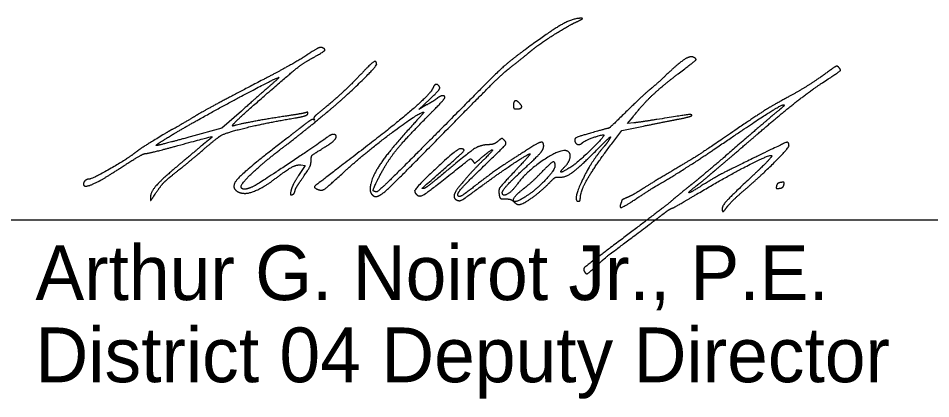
# Model space of a CAD drawing. Extents: x -37878.7 to -37844.7, y -19791.4 to -19769.4.
# Drawn here: x -37851.213 to -37848.88, y -19789.338 to -19788.365 of the extents above; entities that cross this region are included whole.
import ezdxf

# ---------------------------------------------------------------- set-up
doc = ezdxf.new("R2010")
doc.units = 0
doc.layers.add('SH_Data', color=7, linetype='Continuous')
doc.layers.add('SH_Text', color=7, linetype='Continuous')

msp = doc.modelspace()

# ---------------------------------------------------------------- linework, layer by layer
at = {"layer": 'SH_Data'}
msp.add_line((-37851.5558, -19788.88), (-37847.548, -19788.88), dxfattribs=at)
at = {"layer": 'SH_Text'}
for points in [[(-37850.1687, -19788.5865), (-37850.189, -19788.598), (-37850.1608, -19788.5717)], [(-37850.6424, -19788.6021), (-37850.692, -19788.6462), (-37850.7735, -19788.6683)], [(-37849.6391, -19788.6324), (-37849.6551, -19788.6343), (-37849.6411, -19788.6166)], [(-37849.6931, -19788.6823), (-37849.6701, -19788.6519), (-37849.614, -19788.6405)], [(-37850.4902, -19788.7399), (-37850.4796, -19788.7412), (-37850.4963, -19788.7671)]]:
    msp.add_lwpolyline(points, dxfattribs=at)
for points in [[(-37849.7722, -19788.3649), (-37849.7935, -19788.3641), (-37849.8501, -19788.3958), (-37849.9216, -19788.4485)], [(-37849.8997, -19788.4464), (-37849.8824, -19788.4317), (-37849.8072, -19788.384), (-37849.7868, -19788.3747)], [(-37849.7868, -19788.3747), (-37849.7751, -19788.3694), (-37849.7686, -19788.365), (-37849.7722, -19788.3649)], [(-37850.4368, -19788.4396), (-37850.4404, -19788.4382), (-37850.4559, -19788.446), (-37850.4743, -19788.4584)], [(-37850.458, -19788.465), (-37850.4327, -19788.4511), (-37850.4264, -19788.4436), (-37850.4368, -19788.4396)], [(-37849.9216, -19788.4485), (-37849.9599, -19788.4768), (-37850.0004, -19788.5151), (-37850.13, -19788.6461)], [(-37849.9619, -19788.4963), (-37849.9396, -19788.479), (-37849.9126, -19788.4573), (-37849.8997, -19788.4464)], [(-37850.4743, -19788.4584), (-37850.4916, -19788.4701), (-37850.5425, -19788.4988), (-37850.5876, -19788.5222)], [(-37850.5804, -19788.5604), (-37850.5157, -19788.5041), (-37850.4838, -19788.4792), (-37850.458, -19788.465)], [(-37849.4882, -19788.464), (-37849.4962, -19788.4609), (-37849.5269, -19788.4818), (-37849.558, -19788.5115)], [(-37849.5257, -19788.5069), (-37849.4838, -19788.4752), (-37849.4776, -19788.4681), (-37849.4882, -19788.464)], [(-37850.4215, -19788.6034), (-37850.3837, -19788.5722), (-37850.2969, -19788.4883), (-37850.2969, -19788.4828)], [(-37850.2969, -19788.4828), (-37850.2969, -19788.4721), (-37850.3116, -19788.4809), (-37850.3347, -19788.5057)], [(-37850.114, -19788.6466), (-37850.0415, -19788.5726), (-37849.973, -19788.505), (-37849.9619, -19788.4963)], [(-37849.1355, -19788.4966), (-37849.165, -19788.5184), (-37849.2162, -19788.5511), (-37849.2441, -19788.5662)], [(-37849.1568, -19788.5298), (-37849.1139, -19788.5016), (-37849.1088, -19788.4966), (-37849.1157, -19788.4898)], [(-37849.1157, -19788.4898), (-37849.1189, -19788.4866), (-37849.1244, -19788.4885), (-37849.1355, -19788.4966)], [(-37850.751, -19788.6234), (-37850.674, -19788.5806), (-37850.5486, -19788.5147), (-37850.547, -19788.5163)], [(-37850.547, -19788.5163), (-37850.5464, -19788.5168), (-37850.5565, -19788.5265), (-37850.5694, -19788.5377)], [(-37850.3347, -19788.5057), (-37850.3599, -19788.5327), (-37850.4158, -19788.584), (-37850.4444, -19788.6065)], [(-37849.6411, -19788.6166), (-37849.6163, -19788.5851), (-37849.5671, -19788.5383), (-37849.5257, -19788.5069)], [(-37849.558, -19788.5115), (-37849.5714, -19788.5243), (-37849.5888, -19788.5399), (-37849.5966, -19788.5461)], [(-37850.5876, -19788.5222), (-37850.6636, -19788.5618), (-37850.7426, -19788.6041), (-37850.757, -19788.613)], [(-37850.5694, -19788.5377), (-37850.5823, -19788.5488), (-37850.6152, -19788.5779), (-37850.6424, -19788.6021)], [(-37850.1524, -19788.5427), (-37850.1577, -19788.557), (-37850.2516, -19788.6383), (-37850.3463, -19788.7107)], [(-37850.1608, -19788.5717), (-37850.1432, -19788.5552), (-37850.1338, -19788.5435), (-37850.1356, -19788.5405)], [(-37850.1356, -19788.5405), (-37850.14, -19788.5333), (-37850.1494, -19788.5346), (-37850.1524, -19788.5427)], [(-37849.3198, -19788.6584), (-37849.2655, -19788.6114), (-37849.1892, -19788.5512), (-37849.1568, -19788.5298)], [(-37850.6624, -19788.64), (-37850.6709, -19788.6428), (-37850.6353, -19788.6082), (-37850.5804, -19788.5604)], [(-37850.1219, -19788.5676), (-37850.1219, -19788.5622), (-37850.1347, -19788.5635), (-37850.1419, -19788.5695)], [(-37849.5966, -19788.5461), (-37849.6045, -19788.5523), (-37849.631, -19788.577), (-37849.6557, -19788.6011)], [(-37849.2441, -19788.5662), (-37849.2839, -19788.5876), (-37849.314, -19788.6063), (-37849.3747, -19788.6476)], [(-37850.1699, -19788.6195), (-37850.1435, -19788.5929), (-37850.1219, -19788.5695), (-37850.1219, -19788.5676)], [(-37850.1419, -19788.5695), (-37850.1454, -19788.5725), (-37850.1575, -19788.5801), (-37850.1687, -19788.5865)], [(-37849.9317, -19788.5816), (-37849.9391, -19788.5741), (-37849.9468, -19788.5778), (-37849.9468, -19788.5888)], [(-37849.9468, -19788.5888), (-37849.9468, -19788.5939), (-37849.944, -19788.5967), (-37849.9389, -19788.5967)], [(-37849.9389, -19788.5967), (-37849.9279, -19788.5967), (-37849.9242, -19788.589), (-37849.9317, -19788.5816)], [(-37849.4358, -19788.7013), (-37849.3296, -19788.6289), (-37849.2546, -19788.5815), (-37849.2546, -19788.5868)], [(-37849.2546, -19788.5868), (-37849.2546, -19788.5882), (-37849.2597, -19788.5933), (-37849.2658, -19788.5981)], [(-37850.757, -19788.613), (-37850.774, -19788.6234), (-37850.819, -19788.6496), (-37850.82, -19788.6496)], [(-37850.5412, -19788.699), (-37850.5022, -19788.6692), (-37850.4746, -19788.6471), (-37850.4215, -19788.6034)], [(-37850.4786, -19788.6063), (-37850.4828, -19788.6076), (-37850.5047, -19788.6114), (-37850.5271, -19788.6148)], [(-37850.5059, -19788.6198), (-37850.4879, -19788.6168), (-37850.4738, -19788.6123), (-37850.4728, -19788.6093)], [(-37850.4728, -19788.6093), (-37850.4716, -19788.6057), (-37850.4735, -19788.6047), (-37850.4786, -19788.6063)], [(-37850.4444, -19788.6065), (-37850.4527, -19788.613), (-37850.4584, -19788.6201), (-37850.457, -19788.6224)], [(-37850.3788, -19788.7567), (-37850.3277, -19788.7099), (-37850.1876, -19788.6048), (-37850.1763, -19788.6048)], [(-37850.1763, -19788.6048), (-37850.1751, -19788.6048), (-37850.1872, -19788.619), (-37850.2032, -19788.6364)], [(-37849.6557, -19788.6011), (-37849.6996, -19788.644), (-37849.7011, -19788.645), (-37849.7321, -19788.6536)], [(-37849.4908, -19788.6131), (-37849.4908, -19788.6102), (-37849.5075, -19788.6122), (-37849.5804, -19788.6237)], [(-37849.5244, -19788.6225), (-37849.5059, -19788.6189), (-37849.4908, -19788.6147), (-37849.4908, -19788.6131)], [(-37849.2658, -19788.5981), (-37849.2719, -19788.6029), (-37849.3109, -19788.6362), (-37849.3524, -19788.672)], [(-37850.8598, -19788.6903), (-37850.8643, -19788.6903), (-37850.7979, -19788.6495), (-37850.751, -19788.6234)], [(-37850.698, -19788.6667), (-37850.6861, -19788.6582), (-37850.581, -19788.6325), (-37850.5059, -19788.6198)], [(-37850.5271, -19788.6148), (-37850.5705, -19788.6212), (-37850.6507, -19788.6362), (-37850.6624, -19788.64)], [(-37850.4583, -19788.6241), (-37850.4604, -19788.6228), (-37850.4712, -19788.6289), (-37850.4824, -19788.6377)], [(-37850.457, -19788.6224), (-37850.4556, -19788.6246), (-37850.4562, -19788.6254), (-37850.4583, -19788.6241)], [(-37850.2032, -19788.6364), (-37850.2623, -19788.7003), (-37850.3132, -19788.7767), (-37850.3132, -19788.8014)], [(-37850.2914, -19788.7729), (-37850.2717, -19788.7339), (-37850.226, -19788.6761), (-37850.1699, -19788.6195)], [(-37849.5804, -19788.6237), (-37849.6039, -19788.6274), (-37849.6303, -19788.6313), (-37849.6391, -19788.6324)], [(-37849.614, -19788.6405), (-37849.5832, -19788.6342), (-37849.5428, -19788.6261), (-37849.5244, -19788.6225)], [(-37850.82, -19788.6496), (-37850.8206, -19788.6496), (-37850.831, -19788.6557), (-37850.843, -19788.663)], [(-37850.4824, -19788.6377), (-37850.4935, -19788.6466), (-37850.5126, -19788.6615), (-37850.5249, -19788.6709)], [(-37850.2984, -19788.8206), (-37850.288, -19788.8206), (-37850.2425, -19788.7777), (-37850.114, -19788.6466)], [(-37850.13, -19788.6461), (-37850.2185, -19788.7354), (-37850.293, -19788.8085), (-37850.2957, -19788.8085)], [(-37849.7321, -19788.6536), (-37849.7779, -19788.6662), (-37849.7923, -19788.6729), (-37849.7895, -19788.6802)], [(-37849.3747, -19788.6476), (-37849.4633, -19788.7078), (-37849.4825, -19788.7202), (-37849.5417, -19788.7554)], [(-37849.3727, -19788.7037), (-37849.3492, -19788.6836), (-37849.3254, -19788.6633), (-37849.3198, -19788.6584)], [(-37850.843, -19788.663), (-37850.8944, -19788.6946), (-37850.9019, -19788.6995), (-37850.9181, -19788.7118)], [(-37850.7735, -19788.6683), (-37850.8183, -19788.6804), (-37850.8571, -19788.6903), (-37850.8598, -19788.6903)], [(-37850.8046, -19788.6903), (-37850.7239, -19788.6685), (-37850.7135, -19788.6666), (-37850.7265, -19788.6764)], [(-37850.7463, -19788.7063), (-37850.7264, -19788.6894), (-37850.7047, -19788.6716), (-37850.698, -19788.6667)], [(-37850.7265, -19788.6764), (-37850.7309, -19788.6798), (-37850.7383, -19788.6857), (-37850.7427, -19788.6895)], [(-37850.5249, -19788.6709), (-37850.6297, -19788.7512), (-37850.672, -19788.7973), (-37850.6512, -19788.8084)], [(-37850.4239, -19788.6696), (-37850.4425, -19788.684), (-37850.5965, -19788.7869), (-37850.6092, -19788.7935)], [(-37850.4384, -19788.7), (-37850.4244, -19788.6915), (-37850.4107, -19788.6823), (-37850.4079, -19788.6796)], [(-37850.4079, -19788.6796), (-37850.3953, -19788.6673), (-37850.4094, -19788.6584), (-37850.4239, -19788.6696)], [(-37850.0152, -19788.7357), (-37849.9731, -19788.6952), (-37849.9638, -19788.6842), (-37849.9675, -19788.6797)], [(-37849.9883, -19788.6809), (-37849.9925, -19788.6847), (-37850.0027, -19788.6879), (-37850.0111, -19788.6881)], [(-37849.9675, -19788.6797), (-37849.9737, -19788.6722), (-37849.9791, -19788.6726), (-37849.9883, -19788.6809)], [(-37849.8695, -19788.6912), (-37849.8694, -19788.6819), (-37849.8801, -19788.6816), (-37849.8943, -19788.6904)], [(-37849.7159, -19788.6634), (-37849.713, -19788.6662), (-37849.7837, -19788.7349), (-37849.8001, -19788.7453)], [(-37849.7895, -19788.6802), (-37849.7868, -19788.6871), (-37849.7754, -19788.6883), (-37849.7694, -19788.6823)], [(-37849.7758, -19788.8246), (-37849.7758, -19788.807), (-37849.7375, -19788.7411), (-37849.6931, -19788.6823)], [(-37849.7694, -19788.6823), (-37849.7646, -19788.6776), (-37849.7181, -19788.6611), (-37849.7159, -19788.6634)], [(-37849.7292, -19788.6969), (-37849.7092, -19788.6765), (-37849.6962, -19788.6653), (-37849.7003, -19788.672)], [(-37849.7003, -19788.672), (-37849.7043, -19788.6787), (-37849.7109, -19788.6879), (-37849.7148, -19788.6924)], [(-37849.3524, -19788.672), (-37849.4211, -19788.7313), (-37849.4748, -19788.7768), (-37849.4908, -19788.7893)], [(-37849.2424, -19788.6908), (-37849.2424, -19788.68), (-37849.2563, -19788.6848), (-37849.3309, -19788.7212)], [(-37850.8874, -19788.7107), (-37850.8832, -19788.7107), (-37850.8459, -19788.7015), (-37850.8046, -19788.6903)], [(-37850.8013, -19788.7519), (-37850.7909, -19788.7438), (-37850.7662, -19788.7233), (-37850.7463, -19788.7063)], [(-37850.7427, -19788.6895), (-37850.7472, -19788.6934), (-37850.7731, -19788.7153), (-37850.8004, -19788.7382)], [(-37850.643, -19788.7951), (-37850.643, -19788.7874), (-37850.5848, -19788.7324), (-37850.5412, -19788.699)], [(-37850.4639, -19788.7254), (-37850.4639, -19788.7174), (-37850.4586, -19788.7122), (-37850.4384, -19788.7)], [(-37850.0835, -19788.6985), (-37850.0907, -19788.6985), (-37850.1991, -19788.7998), (-37850.1992, -19788.8066)], [(-37850.0111, -19788.6881), (-37850.0317, -19788.6886), (-37850.0632, -19788.7096), (-37850.1439, -19788.7768)], [(-37850.1165, -19788.7434), (-37850.0785, -19788.7101), (-37850.0699, -19788.6985), (-37850.0835, -19788.6985)], [(-37850.032, -19788.724), (-37850.0057, -19788.7012), (-37849.9968, -19788.7011), (-37850.0201, -19788.7239)], [(-37849.8943, -19788.6904), (-37849.9502, -19788.7253), (-37850.0034, -19788.7612), (-37850.03, -19788.7819)], [(-37849.8101, -19788.7041), (-37849.8261, -19788.698), (-37849.9149, -19788.7576), (-37849.9375, -19788.7897)], [(-37849.908, -19788.7389), (-37849.8846, -19788.7174), (-37849.8696, -19788.6987), (-37849.8695, -19788.6912)], [(-37849.8292, -19788.771), (-37849.8144, -19788.7726), (-37849.7745, -19788.743), (-37849.7292, -19788.6969)], [(-37849.8152, -19788.7441), (-37849.8031, -19788.7314), (-37849.8001, -19788.708), (-37849.8101, -19788.7041)], [(-37849.7148, -19788.6924), (-37849.7481, -19788.7303), (-37849.796, -19788.8328), (-37849.7804, -19788.8328)], [(-37849.5824, -19788.7939), (-37849.5597, -19788.7814), (-37849.4717, -19788.7258), (-37849.4358, -19788.7013)], [(-37849.4375, -19788.759), (-37849.4254, -19788.7486), (-37849.3962, -19788.7237), (-37849.3727, -19788.7037)], [(-37849.3585, -19788.806), (-37849.3178, -19788.7711), (-37849.2424, -19788.6962), (-37849.2424, -19788.6908)], [(-37850.9181, -19788.7118), (-37850.9373, -19788.7265), (-37851.0233, -19788.7758), (-37851.0297, -19788.7758)], [(-37850.942, -19788.7413), (-37850.9161, -19788.7245), (-37850.8916, -19788.7107), (-37850.8874, -19788.7107)], [(-37850.4902, -19788.7794), (-37850.4717, -19788.7535), (-37850.4639, -19788.7373), (-37850.4639, -19788.7254)], [(-37850.3463, -19788.7107), (-37850.4516, -19788.7912), (-37850.4587, -19788.7978), (-37850.4458, -19788.8028)], [(-37850.1074, -19788.7633), (-37850.0614, -19788.7266), (-37850.0555, -19788.723), (-37850.051, -19788.7292)], [(-37850.0201, -19788.7239), (-37850.0415, -19788.7448), (-37850.0646, -19788.7699), (-37850.0841, -19788.7933)], [(-37850.051, -19788.7292), (-37850.0463, -19788.7355), (-37850.0447, -19788.7351), (-37850.032, -19788.724)], [(-37850.0268, -19788.7925), (-37849.983, -19788.7602), (-37849.9061, -19788.7093), (-37849.9041, -19788.7113)], [(-37849.9041, -19788.7113), (-37849.9034, -19788.7121), (-37849.92, -19788.731), (-37849.9411, -19788.7534)], [(-37849.4786, -19788.8148), (-37849.3969, -19788.7661), (-37849.2813, -19788.7078), (-37849.2868, -19788.718)], [(-37849.3309, -19788.7212), (-37849.4051, -19788.7575), (-37849.4343, -19788.7732), (-37849.4759, -19788.7992)], [(-37849.2868, -19788.718), (-37849.2891, -19788.7224), (-37849.3149, -19788.7484), (-37849.3441, -19788.7759)], [(-37851.0079, -19788.782), (-37850.9974, -19788.7764), (-37850.9678, -19788.7581), (-37850.942, -19788.7413)], [(-37850.8004, -19788.7382), (-37850.8458, -19788.7764), (-37850.8751, -19788.8098), (-37850.8751, -19788.8233)], [(-37850.8608, -19788.8115), (-37850.8486, -19788.7928), (-37850.831, -19788.7751), (-37850.8013, -19788.7519)], [(-37850.5575, -19788.7762), (-37850.527, -19788.7527), (-37850.5009, -19788.7386), (-37850.4902, -19788.7399)], [(-37850.1764, -19788.8001), (-37850.1811, -19788.8), (-37850.1797, -19788.7987), (-37850.1165, -19788.7434)], [(-37850.088, -19788.8192), (-37850.0925, -19788.8147), (-37850.0676, -19788.7861), (-37850.0152, -19788.7357)], [(-37849.9411, -19788.7534), (-37849.9787, -19788.7933), (-37849.9856, -19788.8043), (-37849.9827, -19788.8193)], [(-37849.9753, -19788.8105), (-37849.9753, -19788.805), (-37849.9468, -19788.7747), (-37849.908, -19788.7389)], [(-37849.8409, -19788.7435), (-37849.8409, -19788.7529), (-37849.8874, -19788.802), (-37849.9117, -19788.8182)], [(-37849.876, -19788.7598), (-37849.851, -19788.7341), (-37849.8409, -19788.7293), (-37849.8409, -19788.7435)], [(-37849.8001, -19788.7453), (-37849.8216, -19788.7588), (-37849.8288, -19788.7582), (-37849.8152, -19788.7441)], [(-37851.0297, -19788.7758), (-37851.0366, -19788.7758), (-37851.0461, -19788.7833), (-37851.0461, -19788.7889)], [(-37850.6326, -19788.8125), (-37850.6201, -19788.8125), (-37850.5787, -19788.7925), (-37850.5575, -19788.7762)], [(-37850.4963, -19788.7671), (-37850.5055, -19788.7813), (-37850.5142, -19788.7985), (-37850.5156, -19788.8053)], [(-37850.4458, -19788.8028), (-37850.4366, -19788.8063), (-37850.4221, -19788.7964), (-37850.3788, -19788.7567)], [(-37850.2957, -19788.8085), (-37850.3059, -19788.8083), (-37850.3049, -19788.7996), (-37850.2914, -19788.7729)], [(-37850.1945, -19788.8155), (-37850.1873, -19788.8227), (-37850.1656, -19788.8097), (-37850.1074, -19788.7633)], [(-37850.1439, -19788.7768), (-37850.1593, -19788.7897), (-37850.174, -19788.8002), (-37850.1764, -19788.8001)], [(-37849.9193, -19788.7993), (-37849.9087, -19788.7912), (-37849.8892, -19788.7734), (-37849.876, -19788.7598)], [(-37849.8577, -19788.7882), (-37849.8442, -19788.7744), (-37849.8373, -19788.7702), (-37849.8292, -19788.771)], [(-37849.5417, -19788.7554), (-37849.573, -19788.774), (-37849.6083, -19788.7955), (-37849.62, -19788.8031)], [(-37849.4773, -19788.7917), (-37849.4675, -19788.7841), (-37849.4496, -19788.7694), (-37849.4375, -19788.759)], [(-37849.3441, -19788.7759), (-37849.3954, -19788.8241), (-37849.4157, -19788.8484), (-37849.4126, -19788.8576)], [(-37851.0461, -19788.7889), (-37851.0461, -19788.7954), (-37851.0265, -19788.7919), (-37851.0079, -19788.782)], [(-37850.6092, -19788.7935), (-37850.6246, -19788.8015), (-37850.643, -19788.8024), (-37850.643, -19788.7951)], [(-37850.5052, -19788.806), (-37850.5044, -19788.8017), (-37850.4976, -19788.7897), (-37850.4902, -19788.7794)], [(-37850.0841, -19788.7933), (-37850.0959, -19788.8075), (-37850.1002, -19788.8245), (-37850.0931, -19788.8289)], [(-37850.0931, -19788.8289), (-37850.0859, -19788.8334), (-37850.0715, -19788.8255), (-37850.0268, -19788.7925)], [(-37850.03, -19788.7819), (-37850.0679, -19788.8116), (-37850.0848, -19788.8224), (-37850.088, -19788.8192)], [(-37849.9375, -19788.7897), (-37849.9504, -19788.8079), (-37849.9753, -19788.8217), (-37849.9753, -19788.8105)], [(-37849.9117, -19788.8182), (-37849.9435, -19788.8394), (-37849.9501, -19788.823), (-37849.9193, -19788.7993)], [(-37849.933, -19788.841), (-37849.924, -19788.841), (-37849.8772, -19788.8082), (-37849.8577, -19788.7882)], [(-37849.6259, -19788.8217), (-37849.6065, -19788.8089), (-37849.5869, -19788.7964), (-37849.5824, -19788.7939)], [(-37849.4908, -19788.7893), (-37849.5032, -19788.799), (-37849.5417, -19788.8307), (-37849.5437, -19788.8329)], [(-37849.4759, -19788.7992), (-37849.4977, -19788.8129), (-37849.4986, -19788.8083), (-37849.4773, -19788.7917)], [(-37849.2743, -19788.7935), (-37849.2754, -19788.7992), (-37849.2736, -19788.8006), (-37849.2662, -19788.7996)], [(-37849.2634, -19788.7847), (-37849.2687, -19788.7854), (-37849.2735, -19788.7893), (-37849.2743, -19788.7935)], [(-37849.2662, -19788.7996), (-37849.261, -19788.7988), (-37849.2561, -19788.7949), (-37849.2553, -19788.7908)], [(-37849.2553, -19788.7908), (-37849.2542, -19788.785), (-37849.2561, -19788.7836), (-37849.2634, -19788.7847)], [(-37850.8751, -19788.8233), (-37850.8751, -19788.8318), (-37850.8729, -19788.83), (-37850.8608, -19788.8115)], [(-37850.6512, -19788.8084), (-37850.647, -19788.8106), (-37850.6386, -19788.8125), (-37850.6326, -19788.8125)], [(-37850.5156, -19788.8053), (-37850.5174, -19788.8148), (-37850.5167, -19788.8172), (-37850.5123, -19788.8157)], [(-37850.5123, -19788.8157), (-37850.5092, -19788.8147), (-37850.506, -19788.8103), (-37850.5052, -19788.806)], [(-37850.3132, -19788.8014), (-37850.3132, -19788.8066), (-37850.311, -19788.813), (-37850.3083, -19788.8157)], [(-37850.3083, -19788.8157), (-37850.3056, -19788.8184), (-37850.3012, -19788.8206), (-37850.2984, -19788.8206)], [(-37850.1992, -19788.8066), (-37850.1992, -19788.8089), (-37850.1971, -19788.8129), (-37850.1945, -19788.8155)], [(-37849.9827, -19788.8193), (-37849.9816, -19788.8248), (-37849.9775, -19788.8267), (-37849.9671, -19788.8266)], [(-37849.6724, -19788.8386), (-37849.6771, -19788.8509), (-37849.6617, -19788.8453), (-37849.6259, -19788.8217)], [(-37849.6556, -19788.8229), (-37849.6635, -19788.8262), (-37849.6699, -19788.8296), (-37849.6699, -19788.8305)], [(-37849.62, -19788.8031), (-37849.6317, -19788.8107), (-37849.6478, -19788.8196), (-37849.6556, -19788.8229)], [(-37849.5418, -19788.8507), (-37849.5395, -19788.8503), (-37849.511, -19788.8341), (-37849.4786, -19788.8148)], [(-37849.4011, -19788.848), (-37849.3956, -19788.8403), (-37849.3764, -19788.8214), (-37849.3585, -19788.806)], [(-37849.9671, -19788.8266), (-37849.959, -19788.8266), (-37849.95, -19788.8296), (-37849.9459, -19788.8338)], [(-37849.9459, -19788.8338), (-37849.9419, -19788.8377), (-37849.9361, -19788.841), (-37849.933, -19788.841)], [(-37849.7804, -19788.8328), (-37849.7779, -19788.8328), (-37849.7758, -19788.8291), (-37849.7758, -19788.8246)], [(-37849.5437, -19788.8329), (-37849.546, -19788.8355), (-37849.6282, -19788.8983), (-37849.6984, -19788.9512)], [(-37849.6699, -19788.8305), (-37849.6699, -19788.8314), (-37849.671, -19788.8351), (-37849.6724, -19788.8386)], [(-37849.5946, -19788.8885), (-37849.5834, -19788.8801), (-37849.5679, -19788.8683), (-37849.5601, -19788.8623)], [(-37849.5601, -19788.8623), (-37849.5523, -19788.8563), (-37849.5441, -19788.851), (-37849.5418, -19788.8507)], [(-37849.4126, -19788.8576), (-37849.4118, -19788.86), (-37849.4066, -19788.8557), (-37849.4011, -19788.848)], [(-37849.7354, -19788.9987), (-37849.7108, -19788.9761), (-37849.7033, -19788.9702), (-37849.5946, -19788.8885)], [(-37849.6984, -19788.9512), (-37849.7589, -19788.9968), (-37849.7693, -19789.006), (-37849.7659, -19789.0115)], [(-37849.7659, -19789.0115), (-37849.7611, -19789.0193), (-37849.7549, -19789.0166), (-37849.7354, -19788.9987)]]:
    msp.add_open_spline(points, degree=2, dxfattribs=at)

# ---------------------------------------------------------------- texts
for s, p in [('Arthur G. Noirot Jr., P.E.', (-37851.1691, -19789.0854)), ('District 04 Deputy Director', (-37851.1691, -19789.2954))]:
    msp.add_text(s, height=0.14, dxfattribs=at).set_placement(p)

doc.saveas('drawing.dxf')
